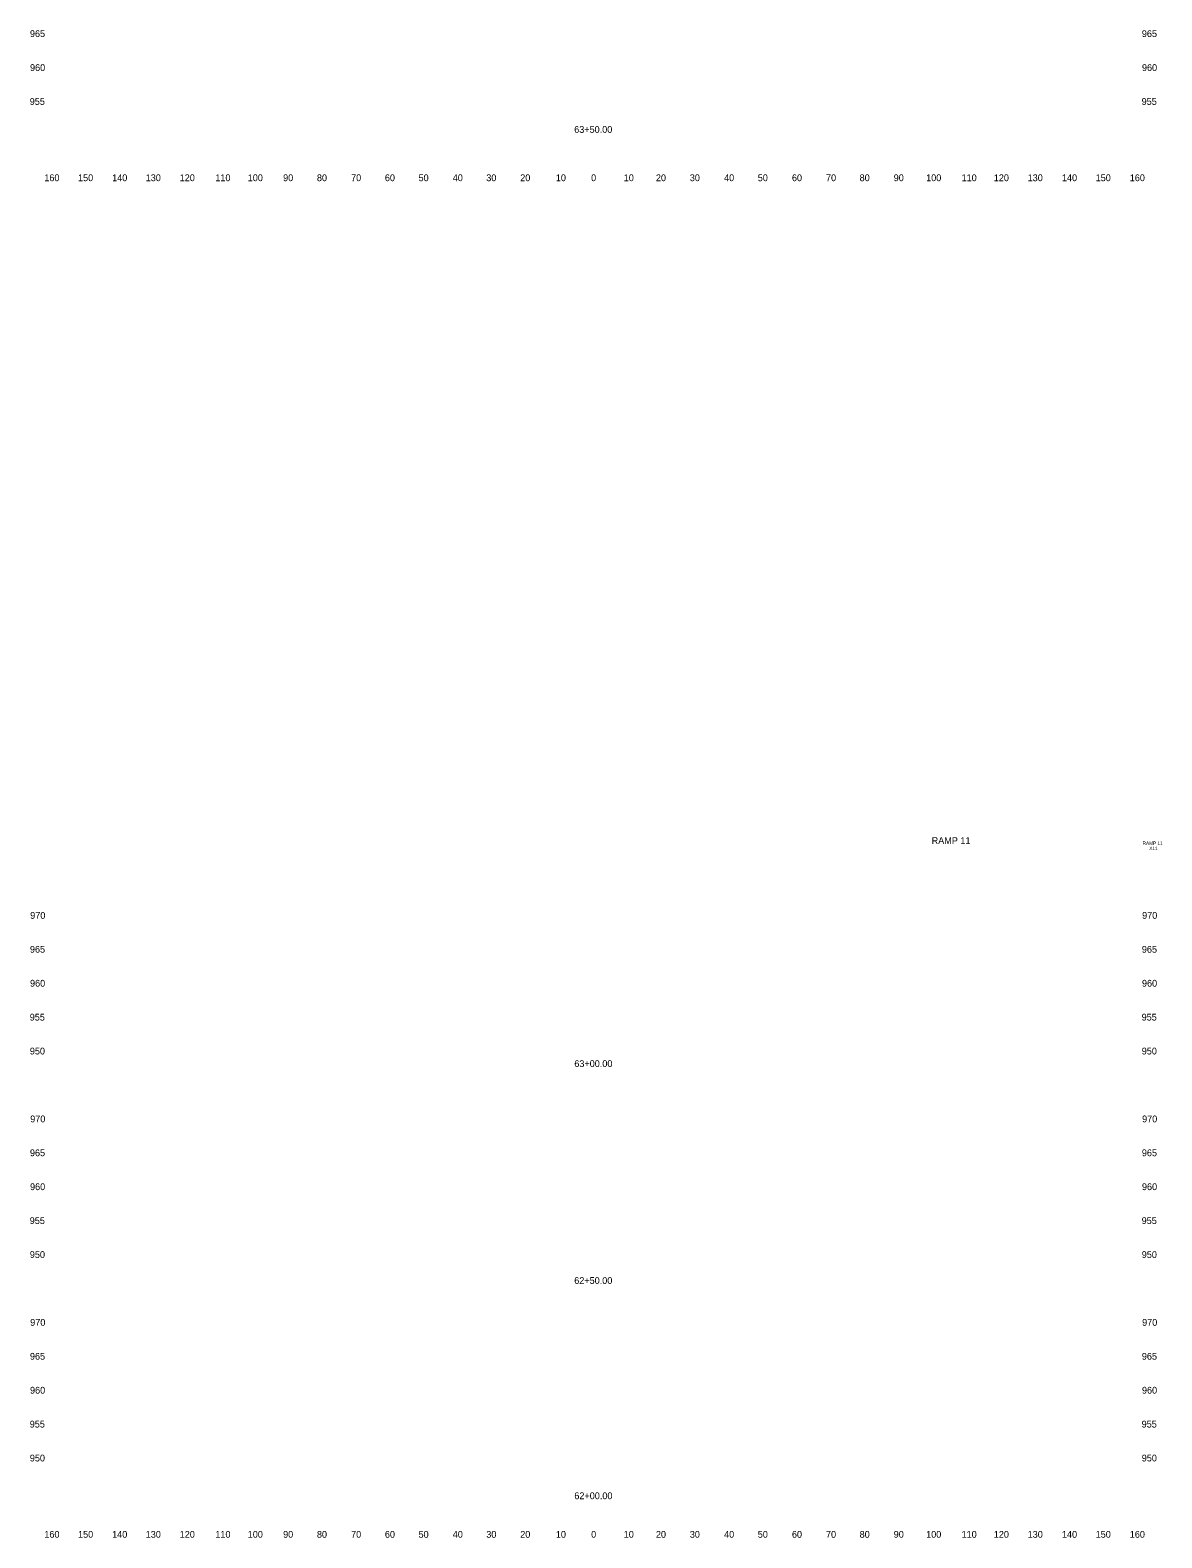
# Model space of a CAD drawing. Extents: x 4994 to 5843, y 4997 to 8804.
# Drawn here: x 5508.9 to 5842.6, y 4997.5 to 5442 of the extents above; entities that cross this region are included whole.
import ezdxf

# ---------------------------------------------------------------- set-up
doc = ezdxf.new("R2010")
doc.units = 0
for name, color, linetype in [('RD_SHT_ID', 7, 'Continuous'), ('RD_XS_TX_Offset', 7, 'Continuous'), ('RD_XS_TX_Station', 7, 'Continuous')]:
    doc.layers.add(name, color=color, linetype=linetype)

msp = doc.modelspace()

# ---------------------------------------------------------------- texts
at = {"layer": 'RD_SHT_ID'}
for s, height, p in [('RAMP 11', 2, (5774.69, 5202.06)), ('RAMP 11', 1, (5836.89, 5201.8)), ('X11', 1, (5838.85, 5200.3))]:
    msp.add_text(s, height=height, dxfattribs=at).set_placement(p)
at = {"layer": 'RD_XS_TX_Offset'}
for s, p in [('965', (5508.86, 5440)), ('965', (5836.66, 5440)), ('960', (5508.89, 5430)), ('960', (5836.69, 5430)), ('955', (5508.8, 5420)), ('955', (5836.6, 5420)), ('160', (5513.1, 5397.5)), ('150', (5523.04, 5397.5)), ('140', (5533.1, 5397.5)), ('130', (5542.99, 5397.5)), ('120', (5553.01, 5397.5)), ('110', (5563.51, 5397.5)), ('100', (5573.07, 5397.5)), ('90', (5583.5, 5397.5)), ('80', (5593.46, 5397.5)), ('70', (5603.54, 5397.5)), ('60', (5613.5, 5397.5)), ('50', (5623.43, 5397.5)), ('40', (5633.5, 5397.5)), ('30', (5643.39, 5397.5)), ('20', (5653.4, 5397.5)), ('10', (5663.91, 5397.5)), ('0', (5674.3, 5397.5)), ('0', (5674.3, 5397.5)), ('10', (5683.91, 5397.5)), ('20', (5693.4, 5397.5)), ('30', (5703.39, 5397.5)), ('40', (5713.5, 5397.5)), ('50', (5723.43, 5397.5)), ('60', (5733.5, 5397.5)), ('70', (5743.54, 5397.5)), ('80', (5753.46, 5397.5)), ('90', (5763.5, 5397.5)), ('100', (5773.07, 5397.5)), ('110', (5783.51, 5397.5)), ('120', (5793.01, 5397.5)), ('130', (5802.99, 5397.5)), ('140', (5813.1, 5397.5)), ('150', (5823.04, 5397.5)), ('160', (5833.1, 5397.5)), ('970', (5508.94, 5180)), ('970', (5836.74, 5180)), ('965', (5508.86, 5170)), ('965', (5836.66, 5170)), ('960', (5508.89, 5160)), ('960', (5836.69, 5160)), ('955', (5508.8, 5150)), ('955', (5836.6, 5150)), ('950', (5508.83, 5140)), ('950', (5836.63, 5140)), ('970', (5508.94, 5120)), ('970', (5836.74, 5120)), ('965', (5508.86, 5110)), ('965', (5836.66, 5110)), ('960', (5508.89, 5100)), ('960', (5836.69, 5100)), ('955', (5508.8, 5090)), ('955', (5836.6, 5090)), ('950', (5508.83, 5080)), ('950', (5836.63, 5080)), ('970', (5508.94, 5060)), ('970', (5836.74, 5060)), ('965', (5508.86, 5050)), ('965', (5836.66, 5050)), ('960', (5508.89, 5040)), ('960', (5836.69, 5040)), ('955', (5508.8, 5030)), ('955', (5836.6, 5030)), ('950', (5508.83, 5020)), ('950', (5836.63, 5020)), ('160', (5513.1, 4997.5)), ('150', (5523.04, 4997.5)), ('140', (5533.1, 4997.5)), ('130', (5542.99, 4997.5)), ('120', (5553.01, 4997.5)), ('110', (5563.51, 4997.5)), ('100', (5573.07, 4997.5)), ('90', (5583.5, 4997.5)), ('80', (5593.46, 4997.5)), ('70', (5603.54, 4997.5)), ('60', (5613.5, 4997.5)), ('50', (5623.43, 4997.5)), ('40', (5633.5, 4997.5)), ('30', (5643.39, 4997.5)), ('20', (5653.4, 4997.5)), ('10', (5663.91, 4997.5)), ('0', (5674.3, 4997.5)), ('0', (5674.3, 4997.5)), ('10', (5683.91, 4997.5)), ('20', (5693.4, 4997.5)), ('30', (5703.39, 4997.5)), ('40', (5713.5, 4997.5)), ('50', (5723.43, 4997.5)), ('60', (5733.5, 4997.5)), ('70', (5743.54, 4997.5)), ('80', (5753.46, 4997.5)), ('90', (5763.5, 4997.5)), ('100', (5773.07, 4997.5)), ('110', (5783.51, 4997.5)), ('120', (5793.01, 4997.5)), ('130', (5802.99, 4997.5)), ('140', (5813.1, 4997.5)), ('150', (5823.04, 4997.5)), ('160', (5833.1, 4997.5))]:
    msp.add_text(s, height=2, dxfattribs=at).set_placement(p)
at = {"layer": 'RD_XS_TX_Station'}
for s, p in [('63+50.00', (5669.31, 5411.75)), ('63+00.00', (5669.34, 5136.3)), ('62+50.00', (5669.32, 5072.34)), ('62+00.00', (5669.35, 5008.87))]:
    msp.add_text(s, height=2, dxfattribs=at).set_placement(p)

doc.saveas('drawing.dxf')
